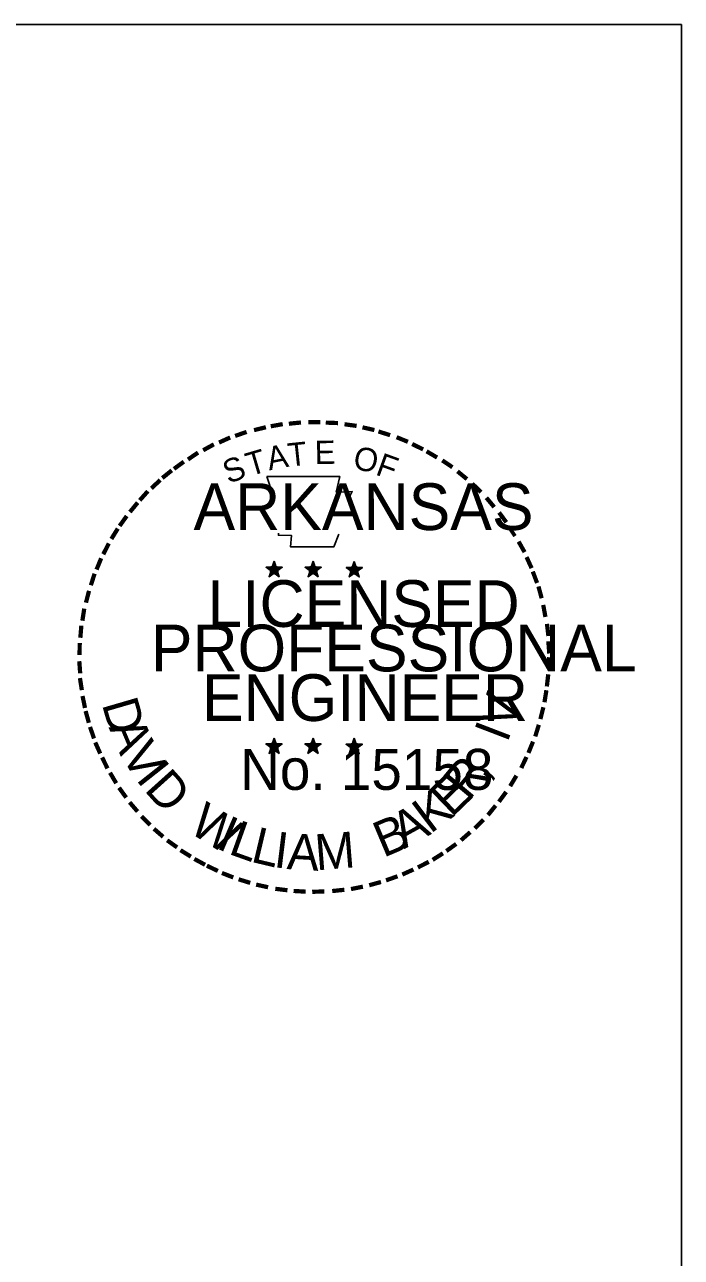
# Model space of a CAD drawing. Extents: x 1416408 to 1429341, y 372694 to 383211.
# Drawn here: x 1428759.6 to 1428995.1, y 374037.9 to 374479.9 of the extents above; entities that cross this region are included whole.
import ezdxf

# ---------------------------------------------------------------- set-up
doc = ezdxf.new("R2010")
doc.units = 0
for name, color, linetype in [('Default', 7, 'Continuous'), ('DSN_DRFT_Junk-No-Plot', 7, 'Continuous'), ('R_Border PE', 7, 'Continuous')]:
    doc.layers.add(name, color=color, linetype=linetype)

msp = doc.modelspace()

# ---------------------------------------------------------------- linework, layer by layer
at = {"layer": 'Default'}
for points in [[(1426234.86, 374479.9), (1426234.86, 372693.86), (1428995.11, 372693.86), (1428995.11, 374479.9)], [(1426234.86, 374479.9), (1426234.86, 372693.86), (1428995.11, 372693.86), (1428995.11, 374479.9)], [(1426234.86, 374479.9), (1428995.11, 374479.9), (1428995.11, 372693.86), (1426234.86, 372693.86)], [(1426234.86, 374479.9), (1426234.86, 372693.86), (1428995.11, 372693.86), (1428995.11, 374479.9)]]:
    msp.add_lwpolyline(points, close=True, dxfattribs=at)
at = {"layer": 'DSN_DRFT_Junk-No-Plot'}
msp.add_lwpolyline([(1426234.86, 374479.9), (1428995.11, 374479.9), (1428995.11, 372693.86), (1426234.86, 372693.86)], close=True, dxfattribs=at)
at = {"layer": 'R_Border PE'}
for p, q in [((1428846.15, 374285.37), (1428849.07, 374284.45)), ((1428846.15, 374285.37), (1428848.27, 374285)), ((1428846.15, 374285.37), (1428848.13, 374284.35)), ((1428847.26, 374281.96), (1428849.07, 374284.45)), ((1428847.26, 374281.96), (1428848.32, 374284)), ((1428847.26, 374281.96), (1428849.06, 374283.78)), ((1428849.07, 374287.5), (1428848.73, 374285.39)), ((1428850.86, 374281.96), (1428849.06, 374283.75)), ((1428849.07, 374284.45), (1428849.07, 374287.5)), ((1428849.07, 374287.5), (1428849.48, 374285.41)), ((1428851.98, 374285.37), (1428849.07, 374284.45)), ((1428850.86, 374281.96), (1428849.07, 374284.45)), ((1428851.98, 374285.37), (1428849.58, 374284.96)), ((1428850.86, 374281.96), (1428849.71, 374284.4)), ((1428851.98, 374285.37), (1428850.27, 374284.52)), ((1428860.13, 374285.37), (1428863.05, 374284.45)), ((1428860.13, 374285.37), (1428862.25, 374285)), ((1428860.13, 374285.37), (1428862.12, 374284.35)), ((1428861.25, 374281.96), (1428863.05, 374284.45)), ((1428861.25, 374281.96), (1428862.3, 374284)), ((1428861.25, 374281.96), (1428863.04, 374283.78)), ((1428863.05, 374287.5), (1428862.71, 374285.39)), ((1428864.84, 374281.96), (1428863.04, 374283.75)), ((1428863.05, 374284.45), (1428863.05, 374287.5)), ((1428863.05, 374287.5), (1428863.46, 374285.41)), ((1428865.96, 374285.37), (1428863.05, 374284.45)), ((1428864.84, 374281.96), (1428863.05, 374284.45)), ((1428865.96, 374285.37), (1428863.56, 374284.96)), ((1428864.84, 374281.96), (1428863.69, 374284.4)), ((1428865.96, 374285.37), (1428864.25, 374284.52)), ((1428874.9, 374285.27), (1428877.82, 374284.34)), ((1428874.9, 374285.27), (1428877.02, 374284.9)), ((1428874.9, 374285.27), (1428876.88, 374284.25)), ((1428876.01, 374281.86), (1428877.82, 374284.34)), ((1428876.01, 374281.86), (1428877.07, 374283.9)), ((1428876.01, 374281.86), (1428877.81, 374283.68)), ((1428877.82, 374287.4), (1428877.48, 374285.29)), ((1428879.61, 374281.86), (1428877.81, 374283.65)), ((1428877.82, 374284.34), (1428877.82, 374287.4)), ((1428877.82, 374287.4), (1428878.23, 374285.31)), ((1428880.73, 374285.27), (1428877.82, 374284.34)), ((1428879.61, 374281.86), (1428877.82, 374284.34)), ((1428880.73, 374285.27), (1428878.33, 374284.86)), ((1428879.61, 374281.86), (1428878.46, 374284.29)), ((1428880.73, 374285.27), (1428879.02, 374284.42)), ((1428846.12, 374221.97), (1428849.04, 374221.04)), ((1428846.12, 374221.97), (1428848.24, 374221.6)), ((1428846.12, 374221.97), (1428848.1, 374220.95)), ((1428849.04, 374224.1), (1428848.7, 374221.99)), ((1428849.04, 374221.04), (1428849.04, 374224.1)), ((1428849.04, 374224.1), (1428849.45, 374222.01)), ((1428851.94, 374221.97), (1428849.04, 374221.04)), ((1428851.94, 374221.97), (1428849.55, 374221.56)), ((1428851.94, 374221.97), (1428850.24, 374221.12)), ((1428860.09, 374221.97), (1428863.01, 374221.04)), ((1428860.09, 374221.97), (1428862.21, 374221.6)), ((1428860.09, 374221.97), (1428862.07, 374220.95)), ((1428863.01, 374224.1), (1428862.67, 374221.99)), ((1428863.01, 374221.04), (1428863.01, 374224.1)), ((1428863.01, 374224.1), (1428863.42, 374222.01)), ((1428865.92, 374221.97), (1428863.01, 374221.04)), ((1428865.92, 374221.97), (1428863.52, 374221.56)), ((1428865.92, 374221.97), (1428864.21, 374221.12)), ((1428874.88, 374221.89), (1428877.81, 374220.96)), ((1428874.88, 374221.89), (1428877, 374221.51)), ((1428874.88, 374221.89), (1428876.87, 374220.87)), ((1428877.81, 374224.02), (1428877.46, 374221.91)), ((1428877.81, 374220.96), (1428877.81, 374224.02)), ((1428877.81, 374224.02), (1428878.22, 374221.92)), ((1428880.71, 374221.89), (1428877.81, 374220.96)), ((1428880.71, 374221.89), (1428878.32, 374221.48)), ((1428880.71, 374221.89), (1428879, 374221.04)), ((1428847.23, 374218.56), (1428849.04, 374221.04)), ((1428847.23, 374218.56), (1428848.29, 374220.6)), ((1428847.23, 374218.56), (1428849.02, 374220.37)), ((1428850.82, 374218.56), (1428849.02, 374220.35)), ((1428850.82, 374218.56), (1428849.04, 374221.04)), ((1428850.82, 374218.56), (1428849.68, 374220.99)), ((1428861.2, 374218.56), (1428863.01, 374221.04)), ((1428861.2, 374218.56), (1428862.26, 374220.6)), ((1428861.2, 374218.56), (1428863, 374220.37)), ((1428864.8, 374218.56), (1428863, 374220.35)), ((1428864.8, 374218.56), (1428863.01, 374221.04)), ((1428864.8, 374218.56), (1428863.65, 374220.99)), ((1428876, 374218.47), (1428877.81, 374220.96)), ((1428876, 374218.47), (1428877.05, 374220.52)), ((1428876, 374218.47), (1428877.79, 374220.29)), ((1428879.59, 374218.47), (1428877.79, 374220.27)), ((1428879.59, 374218.47), (1428877.81, 374220.96)), ((1428879.59, 374218.47), (1428878.44, 374220.91))]:
    msp.add_line(p, q, dxfattribs=at)
for points in [[(1428846.49, 374317.84), (1428848.75, 374310.92)], [(1428875.89, 374310.12), (1428877.08, 374312.5), (1428871.34, 374312.3), (1428872.58, 374317.84), (1428846.49, 374317.84)], [(1428850.61, 374297.56), (1428850.61, 374296.83), (1428855.33, 374296.67), (1428854.87, 374292.71), (1428870.53, 374292.71), (1428872.21, 374297.2)], [(1428849.07, 374287.5), (1428850.86, 374281.96), (1428846.15, 374285.37), (1428851.98, 374285.37), (1428847.26, 374281.96), (1428849.07, 374287.5)], [(1428863.05, 374287.5), (1428864.84, 374281.96), (1428860.13, 374285.37), (1428865.96, 374285.37), (1428861.25, 374281.96), (1428863.05, 374287.5)], [(1428877.82, 374287.4), (1428879.61, 374281.86), (1428874.9, 374285.27), (1428880.73, 374285.27), (1428876.01, 374281.86), (1428877.82, 374287.4)], [(1428849.04, 374224.1), (1428850.82, 374218.56), (1428846.12, 374221.97), (1428851.94, 374221.97), (1428847.23, 374218.56), (1428849.04, 374224.1)], [(1428863.01, 374224.1), (1428864.8, 374218.56), (1428860.09, 374221.97), (1428865.92, 374221.97), (1428861.2, 374218.56), (1428863.01, 374224.1)], [(1428877.81, 374224.02), (1428879.59, 374218.47), (1428874.88, 374221.89), (1428880.71, 374221.89), (1428876, 374218.47), (1428877.81, 374224.02)]]:
    msp.add_lwpolyline(points, dxfattribs=at)
for centre, radius in [((1428849.06, 374284.44), 1.44), ((1428849.06, 374284.44), 1.21), ((1428849.06, 374284.44), 0.969), ((1428849.06, 374284.44), 0.83), ((1428849.06, 374284.44), 0.626), ((1428849.06, 374284.44), 0.415), ((1428849.06, 374284.44), 0.248), ((1428863.05, 374284.44), 1.44), ((1428863.05, 374284.44), 1.21), ((1428863.05, 374284.44), 0.969), ((1428863.05, 374284.44), 0.83), ((1428863.05, 374284.44), 0.626), ((1428863.05, 374284.44), 0.415), ((1428863.05, 374284.44), 0.248), ((1428877.81, 374284.34), 1.44), ((1428877.81, 374284.34), 1.21), ((1428877.81, 374284.34), 0.969), ((1428877.81, 374284.34), 0.83), ((1428877.81, 374284.34), 0.626), ((1428877.81, 374284.34), 0.415), ((1428877.81, 374284.34), 0.248), ((1428849.03, 374221.04), 1.44), ((1428849.03, 374221.04), 1.21), ((1428849.03, 374221.04), 0.969), ((1428849.03, 374221.04), 0.83), ((1428863, 374221.04), 1.44), ((1428863, 374221.04), 1.21), ((1428863, 374221.04), 0.969), ((1428863, 374221.04), 0.83), ((1428877.8, 374220.95), 1.44), ((1428877.8, 374220.95), 1.21), ((1428877.8, 374220.95), 0.969), ((1428877.8, 374220.95), 0.83), ((1428849.03, 374221.04), 0.626), ((1428849.03, 374221.04), 0.415), ((1428849.03, 374221.04), 0.248), ((1428863, 374221.04), 0.626), ((1428863, 374221.04), 0.415), ((1428863, 374221.04), 0.248), ((1428877.8, 374220.95), 0.626), ((1428877.8, 374220.95), 0.415), ((1428877.8, 374220.95), 0.248)]:
    msp.add_circle(centre, radius, dxfattribs=at)

# ---------------------------------------------------------------- texts
for s, height, rotation, p in [('-', 13.4, 10.2193, (1428847.97, 374330.65)), ('-', 13.4, 5.8968, (1428854.07, 374331.57)), ('-', 13.4, 0.1862, (1428860.53, 374332.17)), ('-', 13.4, 357.743, (1428866.59, 374332.07)), ('-', 13.4, 352.1617, (1428872.81, 374331.6)), ('-', 13.4, 24.3072, (1428830.7, 374325.02)), ('-', 13.4, 19.1761, (1428836.01, 374327.28)), ('-', 13.4, 13.6302, (1428842.29, 374329.29)), ('-', 13.4, 347.2049, (1428878.83, 374330.64)), ('-', 13.4, 342.3362, (1428884.15, 374329.34)), ('-', 13.4, 337.8551, (1428890.3, 374327.48)), ('-', 13.4, 28.7918, (1428825.4, 374322.37)), ('T', 8.37, 16.4036, (1428840.37, 374317.92)), ('A', 8.37, 11.2132, (1428847.29, 374320.02)), ('T', 8.37, 6.0228, (1428854.4, 374321.41)), ('E', 8.37, 0.8323, (1428863.65, 374322.33)), ('O', 8.37, 350.4515, (1428877.08, 374320.57)), ('-', 13.4, 334.1211, (1428895.59, 374325.21)), ('-', 13.4, 36.2317, (1428815.57, 374315.97)), ('-', 13.4, 34.0636, (1428820.4, 374319.27)), ('S', 8.37, 21.594, (1428832.72, 374315.15)), ('F', 8.37, 340.0707, (1428885.06, 374318.66)), ('-', 13.4, 329.6409, (1428900.43, 374322.84)), ('-', 13.4, 325.8627, (1428905.82, 374319.82)), ('-', 13.4, 38.9507, (1428811.58, 374312.8)), ('-', 13.4, 320.5297, (1428910.92, 374316.25)), ('-', 13.4, 42.9622, (1428807.96, 374309.31)), ('-', 13.4, 315.5786, (1428915.94, 374312.17)), ('-', 13.4, 48.4231, (1428804.2, 374305.31)), ('-', 13.4, 309.8797, (1428920.7, 374307.56)), ('-', 13.4, 50.6142, (1428800.83, 374301.24)), ('-', 13.4, 54.2325, (1428797.37, 374296.49)), ('-', 13.4, 306.6522, (1428925.1, 374302.52)), ('-', 13.4, 58.0706, (1428794.65, 374292.08)), ('-', 11.72, 303.6753, (1428929.17, 374297.77)), ('-', 13.4, 62.8713, (1428792.03, 374286.94)), ('-', 13.4, 299.6684, (1428931.84, 374292.68)), ('-', 13.4, 67.7743, (1428789.86, 374281.82)), ('-', 13.4, 294.6628, (1428934.55, 374287.56)), ('-', 13.4, 290.5728, (1428936.7, 374282.73)), ('-', 13.4, 72.3945, (1428788.03, 374276.55)), ('-', 13.4, 75.461, (1428786.38, 374270.57)), ('-', 13.4, 285.1233, (1428938.66, 374277.87)), ('-', 13.4, 81.2013, (1428785.28, 374264.6)), ('-', 13.4, 280.5493, (1428940.33, 374271.66)), ('-', 13.4, 85.1863, (1428784.64, 374258.82)), ('-', 13.4, 276.5962, (1428941.69, 374265.23)), ('-', 13.4, 89.0622, (1428784.43, 374252.95)), ('-', 13.4, 274.3301, (1428942.19, 374259.19)), ('-', 13.4, 269.9407, (1428942.48, 374253.9)), ('-', 13.4, 94.1959, (1428784.72, 374246.88)), ('-', 13.4, 98.9479, (1428785.33, 374241.3)), ('-', 13.4, 263.5172, (1428942.32, 374248.32)), ('V', 12.89, 72.6573, (1428934.48, 374226.6)), ('-', 13.4, 260.9953, (1428941.72, 374242.84)), ('-', 13.4, 101.7149, (1428786.46, 374235.16)), ('D', 12.89, 286.2848, (1428787.2, 374236.32)), ('-', 13.4, 255.7626, (1428940.8, 374237.17)), ('-', 13.4, 105.4578, (1428787.81, 374230.18)), ('-', 13.4, 109.0874, (1428789.61, 374224.89)), ('A', 12.89, 292.7835, (1428789.65, 374227.93)), ('I', 12.89, 69.0301, (1428932.62, 374222.09)), ('-', 13.4, 252.8681, (1428939.29, 374231.14)), ('-', 13.4, 114.0643, (1428791.74, 374219.91)), ('V', 12.89, 300.7936, (1428793.95, 374218.05)), ('-', 13.4, 247.8887, (1428937.42, 374225.51)), ('-', 13.4, 115.7289, (1428794.29, 374214.73)), ('-', 13.4, 244.6197, (1428935.23, 374220.24)), ('I', 12.89, 308.3502, (1428799.23, 374209.37)), ('D', 12.89, 311.9774, (1428802.17, 374205.47)), ('R', 12.89, 50.3651, (1428918.8, 374201.25)), ('-', 13.4, 120.4471, (1428797.28, 374209.83)), ('E', 12.89, 44.0175, (1428912.66, 374195.32)), (',', 12.89, 57.4684, (1428924.86, 374208.64)), ('-', 13.4, 239.0712, (1428931.93, 374213.94)), ('-', 13.4, 125.8934, (1428800.66, 374205.13)), ('K', 12.89, 36.9143, (1428905.05, 374189.55)), ('-', 13.4, 233.8452, (1428928.56, 374208.48)), ('-', 13.4, 130.7181, (1428804.52, 374200.51)), ('W', 12.89, 328.0731, (1428817.9, 374190.69)), ('-', 13.4, 231.2538, (1428924.96, 374203.74)), ('-', 13.4, 134.2238, (1428808.85, 374195.94)), ('I', 12.89, 336.6877, (1428827.84, 374184.75)), ('B', 12.89, 22.8589, (1428888.19, 374181.09)), ('A', 12.89, 28.9042, (1428895.69, 374184.22)), ('-', 13.4, 225.7653, (1428920.95, 374199.02)), ('-', 13.4, 138.9338, (1428813.25, 374192.06)), ('L', 12.89, 340.3149, (1428832.27, 374182.71)), ('L', 12.89, 346.6625, (1428840.3, 374179.82)), ('-', 13.4, 221.0851, (1428916.58, 374194.76)), ('-', 13.4, 144.6463, (1428817.9, 374188.66)), ('I', 12.89, 353.0101, (1428848.61, 374177.84)), ('A', 12.89, 356.6373, (1428853.44, 374177.13)), ('M', 12.89, 4.6473, (1428864.19, 374176.64)), ('-', 13.4, 215.7363, (1428911.99, 374190.8)), ('-', 13.4, 148.0898, (1428822.6, 374185.55)), ('-', 13.4, 212.2491, (1428907.52, 374187.56)), ('-', 13.4, 151.5704, (1428827.45, 374182.83)), ('-', 13.4, 154.6002, (1428831.82, 374180.77)), ('-', 13.4, 204.2516, (1428897.62, 374182)), ('-', 13.4, 207.3568, (1428902.84, 374184.67)), ('-', 13.4, 158.5612, (1428837.04, 374178.64)), ('-', 13.4, 162.7983, (1428842.79, 374176.86)), ('-', 13.4, 195.4743, (1428886.77, 374177.68)), ('-', 13.4, 199.4643, (1428892.34, 374179.67)), ('-', 13.4, 167.5555, (1428848.78, 374175.48)), ('-', 13.4, 173.1155, (1428855.24, 374174.56)), ('-', 13.4, 176.5183, (1428861.5, 374174.12)), ('-', 13.4, 181.5918, (1428867.73, 374174.28)), ('-', 13.4, 185.8167, (1428874.51, 374174.91)), ('-', 13.4, 191.2858, (1428880.67, 374176.02))]:
    msp.add_text(s, height=height, rotation=rotation, dxfattribs=at).set_placement(p)
for s, height, p in [('ARKANSAS', 16.744, (1428820.15, 374298.69)), ('LICENSED', 16.744, (1428825.15, 374263.95)), ('PROFESSIONAL', 16.7441, (1428804.86, 374248.01)), ('ENGINEER', 16.744, (1428823.17, 374230.22)), ('No. 15158', 14.71, (1428836.91, 374205.51)), ('AAMU', 0.000167, (1428862.46, 374176.6))]:
    msp.add_text(s, height=height, dxfattribs=at).set_placement(p)

doc.saveas('drawing.dxf')
